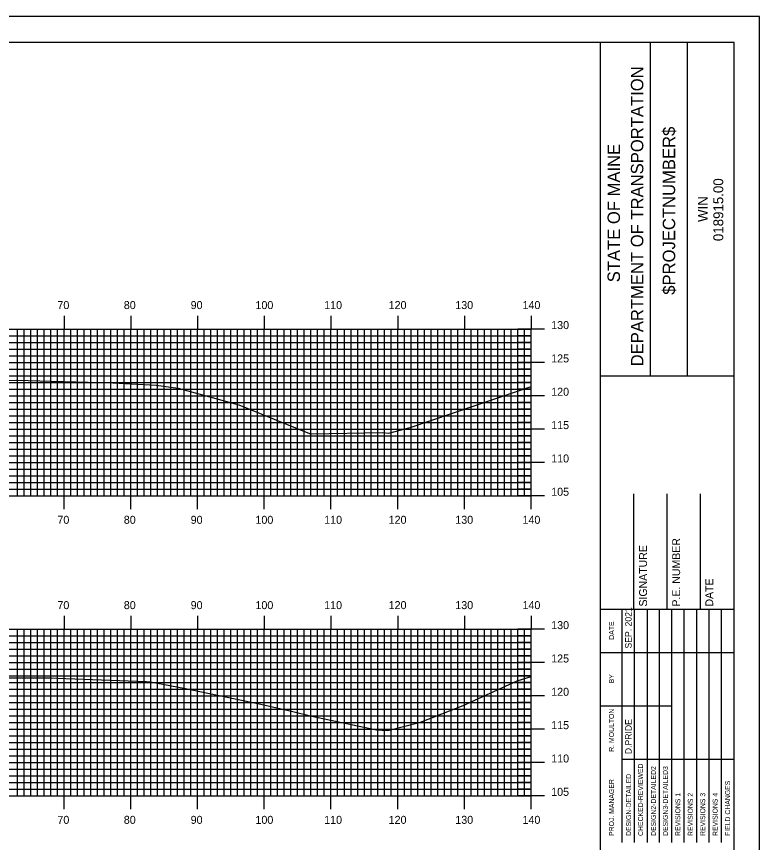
# Model space of a CAD drawing. Extents: x 853894 to 854237, y 366605 to 366825.
# Drawn here: x 854122.4 to 854233.7, y 366701.1 to 366824.9 of the extents above; entities that cross this region are included whole.
import ezdxf

# ---------------------------------------------------------------- set-up
doc = ezdxf.new("R2010")
doc.units = 0
for name, color, linetype in [('BORDER', 7, 'Continuous'), ('H_V ANNOTATION', 7, 'Continuous'), ('MAJOR', 7, 'Continuous'), ('MINOR', 7, 'Continuous'), ('PLOT BOUNDARY', 7, 'Continuous'), ('S_Roadway_Centerline', 7, 'Continuous')]:
    doc.layers.add(name, color=color, linetype=linetype)

msp = doc.modelspace()

# ---------------------------------------------------------------- linework, layer by layer
at = {"layer": 'BORDER'}
for p, q in [((854209.93, 366611.06), (854209.93, 366821.06)), ((854217.39, 366771.05), (854217.39, 366821.05)), ((854222.98, 366771.05), (854222.98, 366821.05)), ((854209.93, 366771.04), (854229.93, 366771.04)), ((854214.93, 366736.06), (854214.93, 366753.36)), ((854219.93, 366736.06), (854219.93, 366753.36)), ((854224.93, 366736.06), (854224.93, 366753.36)), ((854209.93, 366736.06), (854229.93, 366736.06))]:
    msp.add_line(p, q, dxfattribs=at)
msp.add_lwpolyline([(853909.93, 366611.06), (854229.93, 366611.06), (854229.93, 366821.06), (853909.93, 366821.06)], close=True, dxfattribs=at)
for points in [[(854213.16, 366729.56), (854213.16, 366736.06)], [(854215.03, 366701.07), (854215.03, 366736.06)], [(854216.89, 366736.06), (854216.89, 366701.07)], [(854218.75, 366701.07), (854218.75, 366736.06)], [(854220.62, 366701.07), (854220.62, 366736.06)], [(854222.48, 366701.07), (854222.48, 366736.06)], [(854224.34, 366701.07), (854224.34, 366736.06)], [(854226.21, 366701.07), (854226.21, 366736.06)], [(854228.07, 366701.07), (854228.07, 366736.06)], [(854213.16, 366701.07), (854213.16, 366734.65)], [(854209.93, 366729.56), (854229.93, 366729.56)], [(854209.93, 366721.56), (854213.16, 366721.56)], [(854213.16, 366721.56), (854220.61, 366721.56)], [(854213.16, 366713.56), (854229.93, 366713.56)]]:
    msp.add_lwpolyline(points, dxfattribs=at)
at = {"layer": 'MAJOR'}
for p, q in [((854129.53, 366780.06), (854129.53, 366778.06)), ((854139.53, 366780.06), (854139.53, 366778.06)), ((854149.53, 366780.06), (854149.53, 366778.06)), ((854159.53, 366780.06), (854159.53, 366778.06)), ((854169.53, 366780.06), (854169.53, 366778.06)), ((854179.53, 366780.06), (854179.53, 366778.06)), ((854189.53, 366780.06), (854189.53, 366778.06)), ((854199.53, 366780.06), (854199.53, 366778.06)), ((853919.53, 366778.06), (854199.53, 366778.06)), ((853919.53, 366778.06), (854199.53, 366778.06)), ((854129.53, 366753.06), (854129.53, 366778.06)), ((854139.53, 366753.06), (854139.53, 366778.06)), ((854149.53, 366753.06), (854149.53, 366778.06)), ((854159.53, 366753.06), (854159.53, 366778.06)), ((854169.53, 366753.06), (854169.53, 366778.06)), ((854179.53, 366753.06), (854179.53, 366778.06)), ((854189.53, 366753.06), (854189.53, 366778.06)), ((854201.53, 366778.06), (854197.53, 366778.06)), ((854199.53, 366753.06), (854199.53, 366778.06)), ((854199.53, 366753.06), (854199.53, 366778.06)), ((853919.53, 366773.06), (854199.53, 366773.06)), ((854201.53, 366773.06), (854197.53, 366773.06)), ((853919.53, 366768.06), (854199.53, 366768.06)), ((854201.53, 366768.06), (854197.53, 366768.06)), ((853919.53, 366763.06), (854199.53, 366763.06)), ((854201.53, 366763.06), (854197.53, 366763.06)), ((853919.53, 366758.06), (854199.53, 366758.06)), ((854201.53, 366758.06), (854197.53, 366758.06)), ((853919.53, 366753.06), (854199.53, 366753.06)), ((853919.53, 366753.06), (854199.53, 366753.06)), ((854129.53, 366751.05), (854129.53, 366753.06)), ((854139.53, 366751.05), (854139.53, 366753.06)), ((854149.53, 366751.05), (854149.53, 366753.06)), ((854159.53, 366751.05), (854159.53, 366753.06)), ((854169.53, 366751.05), (854169.53, 366753.06)), ((854179.53, 366751.05), (854179.53, 366753.06)), ((854189.53, 366751.05), (854189.53, 366753.06)), ((854201.53, 366753.06), (854197.53, 366753.06)), ((854199.53, 366751.05), (854199.53, 366753.06)), ((854129.53, 366735.06), (854129.53, 366733.06)), ((854139.53, 366735.06), (854139.53, 366733.06)), ((854149.53, 366735.06), (854149.53, 366733.06)), ((854159.53, 366735.06), (854159.53, 366733.06)), ((854169.53, 366735.06), (854169.53, 366733.06)), ((854179.53, 366735.06), (854179.53, 366733.06)), ((854189.53, 366735.06), (854189.53, 366733.06)), ((854199.53, 366735.06), (854199.53, 366733.06)), ((853919.53, 366733.06), (854199.53, 366733.06)), ((853919.53, 366733.06), (854199.53, 366733.06)), ((854129.53, 366708.06), (854129.53, 366733.06)), ((854139.53, 366708.06), (854139.53, 366733.06)), ((854149.53, 366708.06), (854149.53, 366733.06)), ((854159.53, 366708.06), (854159.53, 366733.06)), ((854169.53, 366708.06), (854169.53, 366733.06)), ((854179.53, 366708.06), (854179.53, 366733.06)), ((854189.53, 366708.06), (854189.53, 366733.06)), ((854201.53, 366733.06), (854197.53, 366733.06)), ((854199.53, 366708.06), (854199.53, 366733.06)), ((854199.53, 366708.06), (854199.53, 366733.06)), ((853919.53, 366728.06), (854199.53, 366728.06)), ((854201.53, 366728.06), (854197.53, 366728.06)), ((853919.53, 366723.06), (854199.53, 366723.06)), ((854201.53, 366723.06), (854197.53, 366723.06)), ((853919.53, 366718.06), (854199.53, 366718.06)), ((854201.53, 366718.06), (854197.53, 366718.06)), ((853919.53, 366713.06), (854199.53, 366713.06)), ((854201.53, 366713.06), (854197.53, 366713.06)), ((853919.53, 366708.06), (854199.53, 366708.06)), ((853919.53, 366708.06), (854199.53, 366708.06)), ((854129.53, 366706.05), (854129.53, 366708.06)), ((854139.53, 366706.05), (854139.53, 366708.06)), ((854149.53, 366706.05), (854149.53, 366708.06)), ((854159.53, 366706.05), (854159.53, 366708.06)), ((854169.53, 366706.05), (854169.53, 366708.06)), ((854179.53, 366706.05), (854179.53, 366708.06)), ((854189.53, 366706.05), (854189.53, 366708.06)), ((854201.53, 366708.06), (854197.53, 366708.06)), ((854199.53, 366706.05), (854199.53, 366708.06))]:
    msp.add_line(p, q, dxfattribs=at)
at = {"layer": 'MINOR'}
for p, q in [((854122.53, 366753.06), (854122.53, 366778.06)), ((854123.53, 366753.06), (854123.53, 366778.06)), ((854124.53, 366753.06), (854124.53, 366778.06)), ((854125.53, 366753.06), (854125.53, 366778.06)), ((854126.53, 366753.06), (854126.53, 366778.06)), ((854127.53, 366753.06), (854127.53, 366778.06)), ((854128.53, 366753.06), (854128.53, 366778.06)), ((854130.53, 366753.06), (854130.53, 366778.06)), ((854131.53, 366753.06), (854131.53, 366778.06)), ((854132.53, 366753.06), (854132.53, 366778.06)), ((854133.53, 366753.06), (854133.53, 366778.06)), ((854134.53, 366753.06), (854134.53, 366778.06)), ((854135.53, 366753.06), (854135.53, 366778.06)), ((854136.53, 366753.06), (854136.53, 366778.06)), ((854137.53, 366753.06), (854137.53, 366778.06)), ((854138.53, 366753.06), (854138.53, 366778.06)), ((854140.53, 366753.06), (854140.53, 366778.06)), ((854141.53, 366753.06), (854141.53, 366778.06)), ((854142.53, 366753.06), (854142.53, 366778.06)), ((854143.53, 366753.06), (854143.53, 366778.06)), ((854144.53, 366753.06), (854144.53, 366778.06)), ((854145.53, 366753.06), (854145.53, 366778.06)), ((854146.53, 366753.06), (854146.53, 366778.06)), ((854147.53, 366753.06), (854147.53, 366778.06)), ((854148.53, 366753.06), (854148.53, 366778.06)), ((854150.53, 366753.06), (854150.53, 366778.06)), ((854151.53, 366753.06), (854151.53, 366778.06)), ((854152.53, 366753.06), (854152.53, 366778.06)), ((854153.53, 366753.06), (854153.53, 366778.06)), ((854154.53, 366753.06), (854154.53, 366778.06)), ((854155.53, 366753.06), (854155.53, 366778.06)), ((854156.53, 366753.06), (854156.53, 366778.06)), ((854157.53, 366753.06), (854157.53, 366778.06)), ((854158.53, 366753.06), (854158.53, 366778.06)), ((854160.53, 366753.06), (854160.53, 366778.06)), ((854161.53, 366753.06), (854161.53, 366778.06)), ((854162.53, 366753.06), (854162.53, 366778.06)), ((854163.53, 366753.06), (854163.53, 366778.06)), ((854164.53, 366753.06), (854164.53, 366778.06)), ((854165.53, 366753.06), (854165.53, 366778.06)), ((854166.53, 366753.06), (854166.53, 366778.06)), ((854167.53, 366753.06), (854167.53, 366778.06)), ((854168.53, 366753.06), (854168.53, 366778.06)), ((854170.53, 366753.06), (854170.53, 366778.06)), ((854171.53, 366753.06), (854171.53, 366778.06)), ((854172.53, 366753.06), (854172.53, 366778.06)), ((854173.53, 366753.06), (854173.53, 366778.06)), ((854174.53, 366753.06), (854174.53, 366778.06)), ((854175.53, 366753.06), (854175.53, 366778.06)), ((854176.53, 366753.06), (854176.53, 366778.06)), ((854177.53, 366753.06), (854177.53, 366778.06)), ((854178.53, 366753.06), (854178.53, 366778.06)), ((854180.53, 366753.06), (854180.53, 366778.06)), ((854181.53, 366753.06), (854181.53, 366778.06)), ((854182.53, 366753.06), (854182.53, 366778.06)), ((854183.53, 366753.06), (854183.53, 366778.06)), ((854184.53, 366753.06), (854184.53, 366778.06)), ((854185.53, 366753.06), (854185.53, 366778.06)), ((854186.53, 366753.06), (854186.53, 366778.06)), ((854187.53, 366753.06), (854187.53, 366778.06)), ((854188.53, 366753.06), (854188.53, 366778.06)), ((854190.53, 366753.06), (854190.53, 366778.06)), ((854191.53, 366753.06), (854191.53, 366778.06)), ((854192.53, 366753.06), (854192.53, 366778.06)), ((854193.53, 366753.06), (854193.53, 366778.06)), ((854194.53, 366753.06), (854194.53, 366778.06)), ((854195.53, 366753.06), (854195.53, 366778.06)), ((854196.53, 366753.06), (854196.53, 366778.06)), ((854197.53, 366753.06), (854197.53, 366778.06)), ((854198.53, 366753.06), (854198.53, 366778.06)), ((853919.53, 366777.06), (854199.53, 366777.06)), ((854199.53, 366777.06), (854197.53, 366777.06)), ((853919.53, 366776.06), (854199.53, 366776.06)), ((853919.53, 366775.06), (854199.53, 366775.06)), ((854199.53, 366776.06), (854197.53, 366776.06)), ((854199.53, 366775.06), (854197.53, 366775.06)), ((853919.53, 366774.06), (854199.53, 366774.06)), ((854199.53, 366774.06), (854197.53, 366774.06)), ((853919.53, 366772.06), (854199.53, 366772.06)), ((854199.53, 366772.06), (854197.53, 366772.06)), ((853919.53, 366771.06), (854199.53, 366771.06)), ((853919.53, 366770.06), (854199.53, 366770.06)), ((854199.53, 366771.06), (854197.53, 366771.06)), ((854199.53, 366770.06), (854197.53, 366770.06)), ((853919.53, 366769.06), (854199.53, 366769.06)), ((854199.53, 366769.06), (854197.53, 366769.06)), ((853919.53, 366767.06), (854199.53, 366767.06)), ((854199.53, 366767.06), (854197.53, 366767.06)), ((853919.53, 366766.06), (854199.53, 366766.06)), ((854199.53, 366766.06), (854197.53, 366766.06)), ((853919.53, 366765.06), (854199.53, 366765.06)), ((853919.53, 366764.06), (854199.53, 366764.06)), ((854199.53, 366765.06), (854197.53, 366765.06)), ((854199.53, 366764.06), (854197.53, 366764.06)), ((853919.53, 366762.06), (854199.53, 366762.06)), ((854199.53, 366762.06), (854197.53, 366762.06)), ((853919.53, 366761.06), (854199.53, 366761.06)), ((854199.53, 366761.06), (854197.53, 366761.06)), ((853919.53, 366760.06), (854199.53, 366760.06)), ((853919.53, 366759.06), (854199.53, 366759.06)), ((854199.53, 366760.06), (854197.53, 366760.06)), ((854199.53, 366759.06), (854197.53, 366759.06)), ((853919.53, 366757.06), (854199.53, 366757.06)), ((854199.53, 366757.06), (854197.53, 366757.06)), ((853919.53, 366756.06), (854199.53, 366756.06)), ((854199.53, 366756.06), (854197.53, 366756.06)), ((853919.53, 366755.06), (854199.53, 366755.06)), ((853919.53, 366754.06), (854199.53, 366754.06)), ((854199.53, 366755.06), (854197.53, 366755.06)), ((854199.53, 366754.06), (854197.53, 366754.06)), ((854122.53, 366708.06), (854122.53, 366733.06)), ((854123.53, 366708.06), (854123.53, 366733.06)), ((854124.53, 366708.06), (854124.53, 366733.06)), ((854125.53, 366708.06), (854125.53, 366733.06)), ((854126.53, 366708.06), (854126.53, 366733.06)), ((854127.53, 366708.06), (854127.53, 366733.06)), ((854128.53, 366708.06), (854128.53, 366733.06)), ((854130.53, 366708.06), (854130.53, 366733.06)), ((854131.53, 366708.06), (854131.53, 366733.06)), ((854132.53, 366708.06), (854132.53, 366733.06)), ((854133.53, 366708.06), (854133.53, 366733.06)), ((854134.53, 366708.06), (854134.53, 366733.06)), ((854135.53, 366708.06), (854135.53, 366733.06)), ((854136.53, 366708.06), (854136.53, 366733.06)), ((854137.53, 366708.06), (854137.53, 366733.06)), ((854138.53, 366708.06), (854138.53, 366733.06)), ((854140.53, 366708.06), (854140.53, 366733.06)), ((854141.53, 366708.06), (854141.53, 366733.06)), ((854142.53, 366708.06), (854142.53, 366733.06)), ((854143.53, 366708.06), (854143.53, 366733.06)), ((854144.53, 366708.06), (854144.53, 366733.06)), ((854145.53, 366708.06), (854145.53, 366733.06)), ((854146.53, 366708.06), (854146.53, 366733.06)), ((854147.53, 366708.06), (854147.53, 366733.06)), ((854148.53, 366708.06), (854148.53, 366733.06)), ((854150.53, 366708.06), (854150.53, 366733.06)), ((854151.53, 366708.06), (854151.53, 366733.06)), ((854152.53, 366708.06), (854152.53, 366733.06)), ((854153.53, 366708.06), (854153.53, 366733.06)), ((854154.53, 366708.06), (854154.53, 366733.06)), ((854155.53, 366708.06), (854155.53, 366733.06)), ((854156.53, 366708.06), (854156.53, 366733.06)), ((854157.53, 366708.06), (854157.53, 366733.06)), ((854158.53, 366708.06), (854158.53, 366733.06)), ((854160.53, 366708.06), (854160.53, 366733.06)), ((854161.53, 366708.06), (854161.53, 366733.06)), ((854162.53, 366708.06), (854162.53, 366733.06)), ((854163.53, 366708.06), (854163.53, 366733.06)), ((854164.53, 366708.06), (854164.53, 366733.06)), ((854165.53, 366708.06), (854165.53, 366733.06)), ((854166.53, 366708.06), (854166.53, 366733.06)), ((854167.53, 366708.06), (854167.53, 366733.06)), ((854168.53, 366708.06), (854168.53, 366733.06)), ((854170.53, 366708.06), (854170.53, 366733.06)), ((854171.53, 366708.06), (854171.53, 366733.06)), ((854172.53, 366708.06), (854172.53, 366733.06)), ((854173.53, 366708.06), (854173.53, 366733.06)), ((854174.53, 366708.06), (854174.53, 366733.06)), ((854175.53, 366708.06), (854175.53, 366733.06)), ((854176.53, 366708.06), (854176.53, 366733.06)), ((854177.53, 366708.06), (854177.53, 366733.06)), ((854178.53, 366708.06), (854178.53, 366733.06)), ((854180.53, 366708.06), (854180.53, 366733.06)), ((854181.53, 366708.06), (854181.53, 366733.06)), ((854182.53, 366708.06), (854182.53, 366733.06)), ((854183.53, 366708.06), (854183.53, 366733.06)), ((854184.53, 366708.06), (854184.53, 366733.06)), ((854185.53, 366708.06), (854185.53, 366733.06)), ((854186.53, 366708.06), (854186.53, 366733.06)), ((854187.53, 366708.06), (854187.53, 366733.06)), ((854188.53, 366708.06), (854188.53, 366733.06)), ((854190.53, 366708.06), (854190.53, 366733.06)), ((854191.53, 366708.06), (854191.53, 366733.06)), ((854192.53, 366708.06), (854192.53, 366733.06)), ((854193.53, 366708.06), (854193.53, 366733.06)), ((854194.53, 366708.06), (854194.53, 366733.06)), ((854195.53, 366708.06), (854195.53, 366733.06)), ((854196.53, 366708.06), (854196.53, 366733.06)), ((854197.53, 366708.06), (854197.53, 366733.06)), ((854198.53, 366708.06), (854198.53, 366733.06)), ((853919.53, 366732.06), (854199.53, 366732.06)), ((854199.53, 366732.06), (854197.53, 366732.06)), ((853919.53, 366731.06), (854199.53, 366731.06)), ((854199.53, 366731.06), (854197.53, 366731.06)), ((853919.53, 366730.06), (854199.53, 366730.06)), ((854199.53, 366730.06), (854197.53, 366730.06)), ((853919.53, 366729.06), (854199.53, 366729.06)), ((854199.53, 366729.06), (854197.53, 366729.06)), ((853919.53, 366727.06), (854199.53, 366727.06)), ((854199.53, 366727.06), (854197.53, 366727.06)), ((853919.53, 366726.06), (854199.53, 366726.06)), ((854199.53, 366726.06), (854197.53, 366726.06)), ((853919.53, 366725.06), (854199.53, 366725.06)), ((854199.53, 366725.06), (854197.53, 366725.06)), ((853919.53, 366724.06), (854199.53, 366724.06)), ((854199.53, 366724.06), (854197.53, 366724.06)), ((853919.53, 366722.06), (854199.53, 366722.06)), ((854199.53, 366722.06), (854197.53, 366722.06)), ((853919.53, 366721.06), (854199.53, 366721.06)), ((854199.53, 366721.06), (854197.53, 366721.06)), ((853919.53, 366720.06), (854199.53, 366720.06)), ((854199.53, 366720.06), (854197.53, 366720.06)), ((853919.53, 366719.06), (854199.53, 366719.06)), ((854199.53, 366719.06), (854197.53, 366719.06)), ((853919.53, 366717.06), (854199.53, 366717.06)), ((854199.53, 366717.06), (854197.53, 366717.06)), ((853919.53, 366716.06), (854199.53, 366716.06)), ((854199.53, 366716.06), (854197.53, 366716.06)), ((853919.53, 366715.06), (854199.53, 366715.06)), ((854199.53, 366715.06), (854197.53, 366715.06)), ((853919.53, 366714.06), (854199.53, 366714.06)), ((854199.53, 366714.06), (854197.53, 366714.06)), ((853919.53, 366712.06), (854199.53, 366712.06)), ((854199.53, 366712.06), (854197.53, 366712.06)), ((853919.53, 366711.06), (854199.53, 366711.06)), ((854199.53, 366711.06), (854197.53, 366711.06)), ((853919.53, 366710.06), (854199.53, 366710.06)), ((854199.53, 366710.06), (854197.53, 366710.06)), ((853919.53, 366709.06), (854199.53, 366709.06)), ((854199.53, 366709.06), (854197.53, 366709.06))]:
    msp.add_line(p, q, dxfattribs=at)
at = {"layer": 'PLOT BOUNDARY'}
msp.add_lwpolyline([(853893.74, 366604.94), (854233.74, 366604.94), (854233.74, 366824.94), (853893.74, 366824.94)], close=True, dxfattribs=at)
at = {"layer": 'S_Roadway_Centerline'}
for points in [[(854121.2, 366770.37), (854122.42, 366770.39), (854129.4, 366770.2), (854131.28, 366770.17), (854136.85, 366769.99), (854143.34, 366769.67), (854146.62, 366769.19), (854155.74, 366766.69), (854166.3, 366762.4), (854166.51, 366762.34), (854166.61, 366762.33), (854177.25, 366762.57), (854178.18, 366762.47), (854181.39, 366763.32), (854197.63, 366768.81), (854199.53, 366769.47)], [(854120.89, 366725.77), (854125.93, 366725.77), (854127.66, 366725.75), (854128.43, 366725.71), (854141.81, 366725.19), (854142.47, 366725.16), (854147.49, 366724.23), (854159.01, 366721.79), (854163.8, 366720.71), (854166.68, 366720.03), (854176.33, 366717.98), (854178.05, 366717.87), (854182.95, 366719.12), (854189.34, 366721.63), (854197.45, 366725.33), (854199.53, 366725.96)]]:
    msp.add_lwpolyline(points, dxfattribs=at)

# ---------------------------------------------------------------- texts
at = {"layer": 'BORDER'}
for s, height, p in [('DEPARTMENT OF TRANSPORTATION', 1.8635, (854216.34, 366772.47)), ('$PROJECTNUMBER$', 1.8635, (854221.11, 366783.21)), ('STATE OF MAINE', 1.8635, (854212.84, 366785.08)), ('018915.00', 1.491, (854228.32, 366791.25)), ('WIN', 1.491, (854226, 366794.12)), ('P.E. NUMBER', 1.1811, (854221.85, 366736.45)), ('SIGNATURE', 1.181, (854216.89, 366736.45)), ('DATE', 1.181, (854226.81, 366736.45)), ('SEP. 2021', 0.969, (854214.58, 366730.15)), ('DATE', 0.743, (854211.94, 366731.47)), ('BY', 0.743, (854211.94, 366724.93)), ('R. MOULTON', 0.745, (854211.94, 366714.67)), ('D.PRIDE', 0.969, (854214.58, 366714.31)), ('CHECKED-REVIEWED', 0.7455, (854216.29, 366702.04)), ('DESIGN2-DETAILED2', 0.7455, (854218.23, 366702.04)), ('DESIGN3-DETAILED3', 0.7455, (854220.02, 366702.04)), ('DESIGN-DETAILED', 0.7455, (854214.5, 366702.04)), ('PROJ. MANAGER', 0.7455, (854211.94, 366702.04)), ('FIELD CHANGES', 0.7455, (854229.34, 366702.04)), ('REVISIONS 1', 0.7455, (854221.88, 366702.04)), ('REVISIONS 2', 0.7455, (854223.75, 366702.04)), ('REVISIONS 3', 0.7455, (854225.61, 366702.04)), ('REVISIONS 4', 0.7455, (854227.47, 366702.04))]:
    msp.add_text(s, height=height, rotation=90, dxfattribs=at).set_placement(p)
at = {"layer": 'H_V ANNOTATION'}
for s, p in [('70', (854128.53, 366781.06)), ('80', (854138.48, 366781.06)), ('90', (854148.5, 366781.06)), ('100', (854158.21, 366781.06)), ('110', (854168.51, 366781.06)), ('120', (854178.17, 366781.06)), ('130', (854188.16, 366781.06)), ('140', (854198.23, 366781.06)), ('130', (854202.53, 366778.06)), ('125', (854202.53, 366773.06)), ('120', (854202.53, 366768.06)), ('115', (854202.53, 366763.06)), ('110', (854202.53, 366758.06)), ('105', (854202.53, 366753.06)), ('70', (854128.53, 366748.86)), ('80', (854138.48, 366748.86)), ('90', (854148.5, 366748.86)), ('100', (854158.21, 366748.86)), ('110', (854168.51, 366748.86)), ('120', (854178.17, 366748.86)), ('130', (854188.16, 366748.86)), ('140', (854198.23, 366748.86)), ('70', (854128.53, 366736.06)), ('80', (854138.48, 366736.06)), ('90', (854148.5, 366736.06)), ('100', (854158.21, 366736.06)), ('110', (854168.51, 366736.06)), ('120', (854178.17, 366736.06)), ('130', (854188.16, 366736.06)), ('140', (854198.23, 366736.06)), ('130', (854202.53, 366733.06)), ('125', (854202.53, 366728.06)), ('120', (854202.53, 366723.06)), ('115', (854202.53, 366718.06)), ('110', (854202.53, 366713.06)), ('105', (854202.53, 366708.06)), ('70', (854128.53, 366703.86)), ('80', (854138.48, 366703.86)), ('90', (854148.5, 366703.86)), ('100', (854158.21, 366703.86)), ('110', (854168.51, 366703.86)), ('120', (854178.17, 366703.86)), ('130', (854188.16, 366703.86)), ('140', (854198.23, 366703.86))]:
    msp.add_text(s, height=1.2, dxfattribs=at).set_placement(p)

doc.saveas('drawing.dxf')
